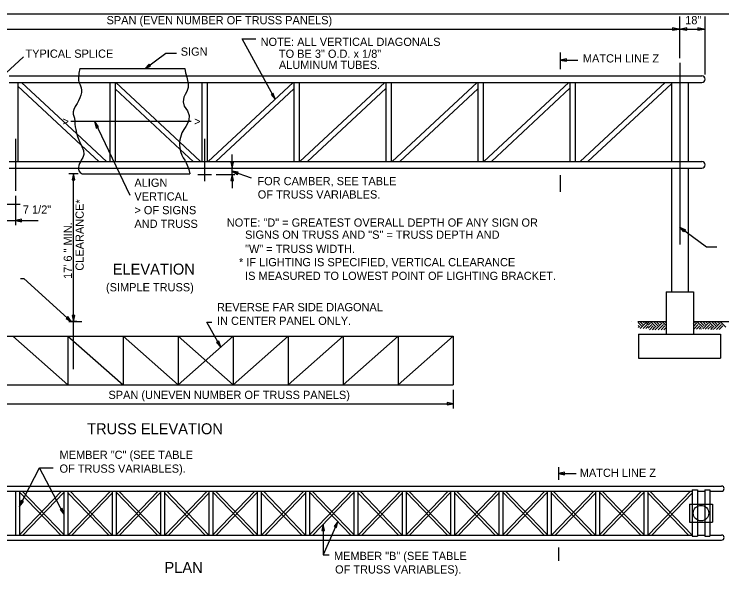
# Model space of a CAD drawing. Extents: x -439 to -407.7, y -458.3 to -438.
# Drawn here: x -432.3 to -419.36, y -448.23 to -437.96 of the extents above; entities that cross this region are included whole.
import ezdxf

# ---------------------------------------------------------------- set-up
doc = ezdxf.new("R2010")
doc.units = 0
doc.layers.add('Draft_Named_Boundary', color=7, linetype='Continuous')
doc.layers.add('Level 4', color=7, linetype='Continuous')

msp = doc.modelspace()

# ---------------------------------------------------------------- linework, layer by layer
at = {"layer": 'Draft_Named_Boundary'}
msp.add_lwpolyline([(-438.987, -458.333), (-407.737, -458.333), (-407.737, -437.958), (-438.987, -437.958)], close=True, dxfattribs=at)
at = {"layer": 'Level 4'}
for p, q in [((-420.13, -438.759), (-420.13, -438.003)), ((-419.668, -439.06), (-419.668, -438.003)), ((-437.735, -438.229), (-420.13, -438.229)), ((-420.13, -438.229), (-419.668, -438.229)), ((-427.528, -439.512), (-428.131, -438.406)), ((-428.131, -438.406), (-427.88, -438.406)), ((-432.447, -439.037), (-432.127, -438.737)), ((-429.905, -438.952), (-429.527, -438.672)), ((-429.527, -438.672), (-429.332, -438.672)), ((-422.314, -438.655), (-422.314, -438.96)), ((-422.314, -438.796), (-421.991, -438.796)), ((-420.13, -438.847), (-420.13, -442.164)), ((-431.095, -438.952), (-429.178, -438.952)), ((-432.39, -439.084), (-431.116, -439.084)), ((-431.116, -439.084), (-429.15, -439.084)), ((-429.15, -439.084), (-419.727, -439.084)), ((-432.39, -439.203), (-431.112, -439.203)), ((-432.227, -439.203), (-432.227, -440.651)), ((-432.227, -439.274), (-431.071, -440.351)), ((-432.164, -439.203), (-431.153, -440.145)), ((-431.112, -439.203), (-429.117, -439.203)), ((-430.545, -439.203), (-430.545, -440.651)), ((-430.45, -439.203), (-430.45, -440.651)), ((-430.44, -439.203), (-429.276, -440.288)), ((-429.117, -439.203), (-419.727, -439.203)), ((-428.864, -439.203), (-428.864, -440.651)), ((-428.769, -439.203), (-428.769, -440.651)), ((-428.749, -440.651), (-427.197, -439.203)), ((-427.183, -439.203), (-427.183, -440.651)), ((-427.088, -439.203), (-427.088, -440.651)), ((-427.074, -440.651), (-425.522, -439.203)), ((-425.501, -439.203), (-425.501, -440.651)), ((-425.406, -439.203), (-425.406, -440.651)), ((-425.385, -440.651), (-423.832, -439.203)), ((-423.82, -439.203), (-423.82, -440.651)), ((-423.725, -439.203), (-423.725, -440.651)), ((-423.713, -440.651), (-422.16, -439.203)), ((-422.138, -439.203), (-422.138, -440.651)), ((-422.043, -439.203), (-422.043, -440.651)), ((-421.949, -440.651), (-420.396, -439.203)), ((-421.81, -440.651), (-420.284, -439.228)), ((-420.284, -439.203), (-420.284, -440.651)), ((-419.977, -439.203), (-419.977, -440.651)), ((-430.45, -439.323), (-429.265, -440.429)), ((-428.61, -440.651), (-427.183, -439.32)), ((-426.935, -440.651), (-425.501, -439.314)), ((-425.245, -440.651), (-423.82, -439.321)), ((-423.573, -440.651), (-422.138, -439.312)), ((-431.259, -439.914), (-429.06, -439.914)), ((-430.831, -439.914), (-430.185, -441.266)), ((-431.153, -440.145), (-430.611, -440.651)), ((-432.274, -440.235), (-432.274, -441.185)), ((-429.276, -440.288), (-428.888, -440.651)), ((-428.817, -440.235), (-428.817, -440.831)), ((-431.071, -440.351), (-430.75, -440.651)), ((-429.265, -440.429), (-429.027, -440.651)), ((-428.312, -440.77), (-428.312, -440.52)), ((-432.39, -440.651), (-431.086, -440.651)), ((-431.086, -440.651), (-429.164, -440.651)), ((-429.164, -440.651), (-419.727, -440.651)), ((-432.39, -440.769), (-431.119, -440.769)), ((-431.119, -440.769), (-429.112, -440.769)), ((-429.112, -440.769), (-419.727, -440.769)), ((-428.817, -440.76), (-428.817, -441.01)), ((-428.312, -440.886), (-428.312, -440.77)), ((-428.312, -440.828), (-427.964, -440.949)), ((-420.284, -440.769), (-420.284, -443.032)), ((-419.977, -440.769), (-419.977, -443.032)), ((-431.124, -440.875), (-431.298, -440.875)), ((-431.175, -440.875), (-431.273, -440.875)), ((-431.211, -444.442), (-431.211, -440.875)), ((-431.054, -440.875), (-429.085, -440.875)), ((-428.942, -440.885), (-428.692, -440.885)), ((-428.604, -440.886), (-428.265, -440.886)), ((-428.312, -440.886), (-428.312, -441.136)), ((-422.314, -440.9), (-422.314, -441.204)), ((-432.274, -441.273), (-432.274, -441.812)), ((-432.437, -441.429), (-432.187, -441.429)), ((-432.437, -441.725), (-432.274, -441.725)), ((-432.274, -441.725), (-431.856, -441.725)), ((-420.13, -441.848), (-419.641, -442.21)), ((-419.641, -442.21), (-419.453, -442.21)), ((-432.178, -442.785), (-432.121, -442.785)), ((-431.252, -443.571), (-432.121, -442.785)), ((-420.379, -443.032), (-420.379, -443.802)), ((-420.379, -443.032), (-419.882, -443.032)), ((-419.882, -443.032), (-419.882, -443.802)), ((-431.298, -443.571), (-431.061, -443.571)), ((-431.149, -443.571), (-431.271, -443.571)), ((-428.522, -444.039), (-428.772, -443.584)), ((-428.772, -443.584), (-428.682, -443.584)), ((-421.021, -443.571), (-421.021, -443.571)), ((-420.895, -443.571), (-420.707, -443.571)), ((-420.833, -443.651), (-420.891, -443.592)), ((-420.859, -443.677), (-420.891, -443.646)), ((-420.891, -443.682), (-420.886, -443.677)), ((-420.806, -443.624), (-420.859, -443.571)), ((-420.855, -443.7), (-420.753, -443.598)), ((-420.78, -443.598), (-420.806, -443.571)), ((-420.802, -443.7), (-420.726, -443.624)), ((-420.707, -443.617), (-420.753, -443.571)), ((-420.749, -443.7), (-420.707, -443.657)), ((-420.707, -443.571), (-420.379, -443.571)), ((-420.693, -443.598), (-420.707, -443.584)), ((-420.707, -443.638), (-420.667, -443.598)), ((-420.707, -443.691), (-420.64, -443.624)), ((-420.684, -443.721), (-420.614, -443.651)), ((-420.561, -443.677), (-420.666, -443.571)), ((-420.631, -443.721), (-420.587, -443.677)), ((-420.534, -443.651), (-420.613, -443.571)), ((-420.561, -443.704), (-420.455, -443.598)), ((-420.508, -443.624), (-420.56, -443.571)), ((-420.525, -443.721), (-420.428, -443.624)), ((-420.481, -443.598), (-420.507, -443.571)), ((-420.472, -443.721), (-420.402, -443.651)), ((-420.379, -443.647), (-420.454, -443.571)), ((-420.379, -443.594), (-420.401, -443.571)), ((-419.882, -443.571), (-419.206, -443.571)), ((-419.882, -443.662), (-419.818, -443.598)), ((-419.871, -443.624), (-419.882, -443.613)), ((-419.876, -443.709), (-419.792, -443.624)), ((-419.845, -443.598), (-419.871, -443.571)), ((-419.824, -443.71), (-419.765, -443.651)), ((-419.712, -443.677), (-419.818, -443.571)), ((-419.772, -443.711), (-419.739, -443.677)), ((-419.686, -443.651), (-419.765, -443.571)), ((-419.659, -443.624), (-419.712, -443.571)), ((-419.712, -443.704), (-419.606, -443.598)), ((-419.668, -443.713), (-419.58, -443.624)), ((-419.633, -443.598), (-419.659, -443.571)), ((-419.616, -443.714), (-419.553, -443.651)), ((-419.5, -443.677), (-419.606, -443.571)), ((-419.565, -443.715), (-419.527, -443.677)), ((-419.473, -443.651), (-419.553, -443.571)), ((-419.447, -443.624), (-419.5, -443.571)), ((-419.5, -443.704), (-419.394, -443.598)), ((-419.461, -443.717), (-419.367, -443.624)), ((-419.42, -443.598), (-419.447, -443.571)), ((-419.409, -443.719), (-419.341, -443.651)), ((-419.288, -443.677), (-419.394, -443.571)), ((-420.884, -443.802), (-420.884, -444.239)), ((-420.884, -443.802), (-419.386, -443.802)), ((-420.569, -443.721), (-420.587, -443.704)), ((-420.419, -443.721), (-420.379, -443.681)), ((-419.731, -443.712), (-419.739, -443.704)), ((-419.514, -443.716), (-419.527, -443.704)), ((-419.386, -443.802), (-419.386, -444.239)), ((-433.325, -443.837), (-424.271, -443.837)), ((-431.313, -444.729), (-432.319, -443.837)), ((-431.313, -443.837), (-431.313, -444.729)), ((-431.313, -443.837), (-430.307, -444.729)), ((-430.307, -443.837), (-430.307, -444.729)), ((-430.307, -443.837), (-429.301, -444.729)), ((-428.295, -443.837), (-429.301, -444.729)), ((-429.301, -443.837), (-429.301, -444.729)), ((-429.301, -443.837), (-428.295, -444.729)), ((-428.295, -443.837), (-428.295, -444.729)), ((-428.295, -444.729), (-427.289, -443.837)), ((-427.289, -443.837), (-427.289, -444.729)), ((-426.283, -443.837), (-427.289, -444.729)), ((-426.283, -443.837), (-426.283, -444.729)), ((-425.277, -443.837), (-426.283, -444.729)), ((-425.277, -443.837), (-425.277, -444.729)), ((-424.271, -443.837), (-425.277, -444.729)), ((-424.271, -443.837), (-424.271, -444.729)), ((-420.884, -444.239), (-419.386, -444.239)), ((-433.325, -444.729), (-424.271, -444.729)), ((-424.271, -444.817), (-424.271, -445.16)), ((-433.325, -445.073), (-424.271, -445.073)), ((-432.198, -446.949), (-431.833, -446.241)), ((-431.386, -447.093), (-431.833, -446.241)), ((-431.833, -446.241), (-431.584, -446.241)), ((-422.349, -446.232), (-422.349, -446.464)), ((-422.349, -446.348), (-422.026, -446.348)), ((-432.444, -446.576), (-419.366, -446.576)), ((-419.904, -446.648), (-419.904, -447.494)), ((-419.904, -446.648), (-419.809, -446.648)), ((-419.809, -446.648), (-419.809, -447.494)), ((-419.674, -446.648), (-419.674, -447.494)), ((-419.674, -446.648), (-419.579, -446.648)), ((-419.579, -446.648), (-419.579, -447.494)), ((-432.444, -446.671), (-419.904, -446.671)), ((-432.27, -446.671), (-432.27, -447.471)), ((-432.198, -447.467), (-431.43, -446.671)), ((-432.198, -446.671), (-432.198, -447.471)), ((-432.198, -446.671), (-432.198, -447.471)), ((-432.198, -446.687), (-431.442, -447.471)), ((-432.148, -446.671), (-431.386, -447.46)), ((-432.136, -447.471), (-431.386, -446.694)), ((-431.386, -446.671), (-431.386, -447.471)), ((-431.315, -446.671), (-431.315, -447.471)), ((-431.315, -446.671), (-431.315, -447.471)), ((-431.315, -446.698), (-430.569, -447.471)), ((-431.307, -447.471), (-430.535, -446.671)), ((-431.275, -446.671), (-430.503, -447.471)), ((-431.241, -447.471), (-430.503, -446.707)), ((-430.503, -446.671), (-430.503, -447.471)), ((-430.432, -447.467), (-429.664, -446.671)), ((-430.432, -446.671), (-430.432, -447.471)), ((-430.432, -446.671), (-430.432, -447.471)), ((-430.432, -446.671), (-430.432, -447.471)), ((-430.432, -446.687), (-429.675, -447.471)), ((-430.381, -446.671), (-429.62, -447.46)), ((-430.369, -447.471), (-429.62, -446.694)), ((-429.62, -446.671), (-429.62, -447.471)), ((-429.549, -446.671), (-429.549, -447.471)), ((-429.549, -446.671), (-429.549, -447.471)), ((-429.549, -446.698), (-428.803, -447.471)), ((-429.54, -447.471), (-428.768, -446.671)), ((-429.508, -446.671), (-428.737, -447.471)), ((-429.474, -447.471), (-428.737, -446.707)), ((-428.737, -446.671), (-428.737, -447.471)), ((-428.665, -447.467), (-427.897, -446.671)), ((-428.665, -446.671), (-428.665, -447.471)), ((-428.665, -446.671), (-428.665, -447.471)), ((-428.665, -446.671), (-428.665, -447.471)), ((-428.665, -446.687), (-427.909, -447.471)), ((-428.615, -446.671), (-427.853, -447.46)), ((-428.603, -447.471), (-427.853, -446.694)), ((-427.853, -446.671), (-427.853, -447.471)), ((-427.782, -446.671), (-427.782, -447.471)), ((-427.782, -446.671), (-427.782, -447.471)), ((-427.782, -446.698), (-427.036, -447.471)), ((-427.774, -447.471), (-427.002, -446.671)), ((-427.742, -446.671), (-426.97, -447.471)), ((-427.708, -447.471), (-426.97, -446.707)), ((-426.97, -446.671), (-426.97, -447.471)), ((-426.899, -447.467), (-426.131, -446.671)), ((-426.899, -446.671), (-426.899, -447.471)), ((-426.899, -446.671), (-426.899, -447.471)), ((-426.899, -446.671), (-426.899, -447.471)), ((-426.899, -446.687), (-426.142, -447.471)), ((-426.848, -446.671), (-426.087, -447.46)), ((-426.837, -447.471), (-426.087, -446.694)), ((-426.087, -446.671), (-426.087, -447.471)), ((-426.016, -446.671), (-426.016, -447.471)), ((-426.016, -446.671), (-426.016, -447.471)), ((-426.016, -446.698), (-425.27, -447.471)), ((-426.007, -447.471), (-425.235, -446.671)), ((-425.975, -446.671), (-425.204, -447.471)), ((-425.941, -447.471), (-425.204, -446.707)), ((-425.204, -446.671), (-425.204, -447.471)), ((-425.132, -447.467), (-424.364, -446.671)), ((-425.132, -446.671), (-425.132, -447.471)), ((-425.132, -446.671), (-425.132, -447.471)), ((-425.132, -446.671), (-425.132, -447.471)), ((-425.132, -446.687), (-424.376, -447.471)), ((-425.082, -446.671), (-424.32, -447.46)), ((-425.07, -447.471), (-424.32, -446.694)), ((-424.32, -446.671), (-424.32, -447.471)), ((-424.249, -446.671), (-424.249, -447.471)), ((-424.249, -446.671), (-424.249, -447.471)), ((-424.249, -446.698), (-423.503, -447.471)), ((-424.241, -447.471), (-423.469, -446.671)), ((-424.209, -446.671), (-423.437, -447.471)), ((-424.175, -447.471), (-423.437, -446.707)), ((-423.437, -446.671), (-423.437, -447.471)), ((-423.366, -447.467), (-422.598, -446.671)), ((-423.366, -446.671), (-423.366, -447.471)), ((-423.366, -446.671), (-423.366, -447.471)), ((-423.366, -446.687), (-422.609, -447.471)), ((-423.315, -446.671), (-422.554, -447.46)), ((-423.304, -447.471), (-422.554, -446.694)), ((-422.554, -446.671), (-422.554, -447.471)), ((-422.483, -446.671), (-422.483, -447.471)), ((-422.483, -446.698), (-421.737, -447.471)), ((-422.474, -447.471), (-421.702, -446.671)), ((-422.443, -446.671), (-421.671, -447.471)), ((-422.408, -447.471), (-421.671, -446.707)), ((-421.671, -446.671), (-421.671, -447.471)), ((-421.599, -447.467), (-420.831, -446.671)), ((-421.599, -446.671), (-421.599, -447.471)), ((-421.599, -446.687), (-420.843, -447.471)), ((-421.549, -446.671), (-420.787, -447.46)), ((-421.537, -447.471), (-420.787, -446.694)), ((-420.787, -446.671), (-420.787, -447.471)), ((-420.716, -446.671), (-420.716, -447.471)), ((-420.716, -446.698), (-419.97, -447.471)), ((-420.708, -447.471), (-419.936, -446.671)), ((-420.676, -446.671), (-419.904, -447.471)), ((-420.642, -447.471), (-419.904, -446.707)), ((-419.904, -446.671), (-419.904, -447.471)), ((-419.809, -446.671), (-419.674, -446.671)), ((-419.579, -446.671), (-419.366, -446.671)), ((-419.952, -446.906), (-419.952, -447.236)), ((-419.952, -446.906), (-419.532, -446.906)), ((-419.532, -446.906), (-419.532, -447.236)), ((-426.382, -447.222), (-426.649, -447.835)), ((-426.649, -447.276), (-426.649, -447.835)), ((-419.952, -447.236), (-419.532, -447.236)), ((-432.444, -447.471), (-419.904, -447.471)), ((-419.904, -447.494), (-419.809, -447.494)), ((-419.809, -447.471), (-419.674, -447.471)), ((-419.674, -447.494), (-419.579, -447.494)), ((-419.579, -447.471), (-419.366, -447.471)), ((-432.444, -447.566), (-419.366, -447.566)), ((-422.349, -447.697), (-422.349, -447.945)), ((-426.649, -447.835), (-426.537, -447.835))]:
    msp.add_line(p, q, dxfattribs=at)
for points in [[(-420.261, -438.252), (-420.15, -438.229), (-420.261, -438.206)], [(-420, -438.206), (-420.11, -438.229), (-420, -438.252)], [(-419.799, -438.252), (-419.688, -438.229), (-419.799, -438.206)], [(-429.83, -438.868), (-429.905, -438.952), (-429.802, -438.905)], [(-422.203, -438.773), (-422.314, -438.796), (-422.203, -438.819)], [(-427.601, -439.426), (-427.528, -439.512), (-427.561, -439.404)], [(-430.752, -440.017), (-430.831, -439.914), (-430.8, -440.04)], [(-428.335, -440.659), (-428.312, -440.77), (-428.289, -440.659)], [(-428.2, -440.843), (-428.312, -440.828), (-428.215, -440.886)], [(-431.188, -440.986), (-431.211, -440.875), (-431.234, -440.986)], [(-428.289, -440.996), (-428.312, -440.886), (-428.335, -440.996)], [(-432.164, -441.702), (-432.274, -441.725), (-432.164, -441.748)], [(-420.055, -441.932), (-420.13, -441.848), (-420.027, -441.895)], [(-431.349, -443.514), (-431.252, -443.571), (-431.318, -443.48)], [(-431.234, -443.461), (-431.211, -443.571), (-431.188, -443.461)], [(-428.596, -443.953), (-428.522, -444.039), (-428.556, -443.931)], [(-424.381, -445.096), (-424.271, -445.073), (-424.381, -445.05)], [(-422.238, -446.325), (-422.349, -446.348), (-422.238, -446.371)], [(-432.168, -446.84), (-432.198, -446.949), (-432.127, -446.861)], [(-431.458, -447.006), (-431.386, -447.093), (-431.417, -446.985)], [(-426.626, -447.387), (-426.649, -447.276), (-426.672, -447.387)], [(-426.405, -447.333), (-426.382, -447.222), (-426.448, -447.315)]]:
    msp.add_lwpolyline(points, close=True, dxfattribs=at)
for points in [[(-431.095, -438.952), (-431.112, -439.038), (-431.118, -439.126), (-431.118, -439.165), (-431.112, -439.202), (-431.093, -439.251), (-431.072, -439.301), (-431.064, -439.344), (-431.066, -439.388), (-431.077, -439.438), (-431.095, -439.487), (-431.119, -439.54), (-431.147, -439.591), (-431.179, -439.642), (-431.205, -439.696), (-431.217, -439.739), (-431.217, -439.783), (-431.206, -439.821), (-431.194, -439.858), (-431.188, -439.913), (-431.188, -439.969), (-431.181, -440.018), (-431.17, -440.067), (-431.157, -440.129), (-431.141, -440.189), (-431.104, -440.282), (-431.06, -440.375), (-431.032, -440.448), (-431.025, -440.521), (-431.043, -440.574), (-431.072, -440.625), (-431.087, -440.654), (-431.101, -440.683), (-431.112, -440.72), (-431.118, -440.759), (-431.119, -440.788), (-431.112, -440.817), (-431.089, -440.851), (-431.054, -440.875)], [(-429.178, -438.952), (-429.162, -439.031), (-429.143, -439.109), (-429.126, -439.167), (-429.114, -439.225), (-429.119, -439.299), (-429.143, -439.37), (-429.171, -439.422), (-429.195, -439.475), (-429.209, -439.558), (-429.19, -439.638), (-429.159, -439.681), (-429.126, -439.725), (-429.098, -439.806), (-429.103, -439.893), (-429.127, -439.954), (-429.161, -440.009), (-429.198, -440.066), (-429.23, -440.126), (-429.246, -440.168), (-429.259, -440.213), (-429.27, -440.253), (-429.277, -440.294), (-429.277, -440.346), (-429.271, -440.399), (-429.255, -440.467), (-429.23, -440.532), (-429.205, -440.579), (-429.178, -440.625), (-429.153, -440.671), (-429.132, -440.718), (-429.104, -440.795), (-429.085, -440.875)]]:
    msp.add_lwpolyline(points, dxfattribs=at)
msp.add_circle((-419.742, -447.071), 0.142, dxfattribs=at)
for centre, radius in [((-419.727, -439.144), 0.0594), ((-419.727, -440.71), 0.0594), ((-419.366, -446.624), 0.0475), ((-419.366, -447.518), 0.0475)]:
    msp.add_arc(centre, radius, 270, 90, dxfattribs=at)

# ---------------------------------------------------------------- texts
for s, height, p in [('SPAN (EVEN NUMBER OF TRUSS PANELS)', 0.15, (-430.608, -438.142)), ('18"', 0.15, (-420.031, -438.142)), ('NOTE: ALL VERTICAL DIAGONALS', 0.15, (-427.792, -438.538)), ('TYPICAL SPLICE', 0.15, (-432.09, -438.754)), ('SIGN', 0.15, (-429.252, -438.716)), ('      TO BE 3" O.D. x 1/8"', 0.15, (-427.792, -438.755)), ('MATCH LINE Z', 0.15, (-421.901, -438.84)), ('      ALUMINUM TUBES.', 0.15, (-427.792, -438.958)), ('>', 0.15, (-431.414, -439.989)), ('>', 0.15, (-429.009, -439.989)), ('ALIGN', 0.15, (-430.099, -441.111)), ('FOR CAMBER, SEE TABLE', 0.15, (-427.85, -441.081)), ('VERTICAL', 0.15, (-430.099, -441.361)), ('OF TRUSS VARIABLES.', 0.15, (-427.844, -441.325)), ('7 1/2"', 0.15, (-432.137, -441.601)), ('> OF SIGNS', 0.15, (-430.099, -441.611)), ('AND TRUSS', 0.15, (-430.099, -441.861)), ('NOTE: "D" = GREATEST OVERALL DEPTH OF ANY SIGN OR', 0.15, (-428.41, -441.839)), ('      SIGNS ON TRUSS AND "S" = TRUSS DEPTH AND', 0.15, (-428.41, -442.06)), ('      "W" = TRUSS WIDTH.', 0.15, (-428.41, -442.319)), ('ELEVATION', 0.2, (-430.495, -442.714)), ('    * IF LIGHTING IS SPECIFIED, VERTICAL CLEARANCE', 0.15, (-428.41, -442.562)), ('      IS MEASURED TO LOWEST POINT OF LIGHTING BRACKET.', 0.15, (-428.41, -442.812)), ('(SIMPLE TRUSS)', 0.15, (-430.618, -443.02)), ('REVERSE FAR SIDE DIAGONAL ', 0.15, (-428.589, -443.383)), ('IN CENTER PANEL ONLY.', 0.15, (-428.589, -443.633)), ('SPAN (UNEVEN NUMBER OF TRUSS PANELS)', 0.15, (-430.573, -444.986)), ('TRUSS ELEVATION', 0.2, (-430.963, -445.63)), ('MEMBER "C" (SEE TABLE', 0.15, (-431.467, -446.08)), ('OF TRUSS VARIABLES).', 0.15, (-431.467, -446.333)), ('MATCH LINE Z', 0.15, (-421.958, -446.409)), ('MEMBER "B" (SEE TABLE', 0.15, (-426.451, -447.927)), ('PLAN', 0.2, (-429.549, -448.163)), ('OF TRUSS VARIABLES).', 0.15, (-426.431, -448.174))]:
    msp.add_text(s, height=height, dxfattribs=at).set_placement(p)
for s, p in [('CLEARANCE* ', (-431.025, -442.643)), ('17\' 6 " MIN. ', (-431.241, -442.793))]:
    msp.add_text(s, height=0.15, rotation=90, dxfattribs=at).set_placement(p)

doc.saveas('drawing.dxf')
